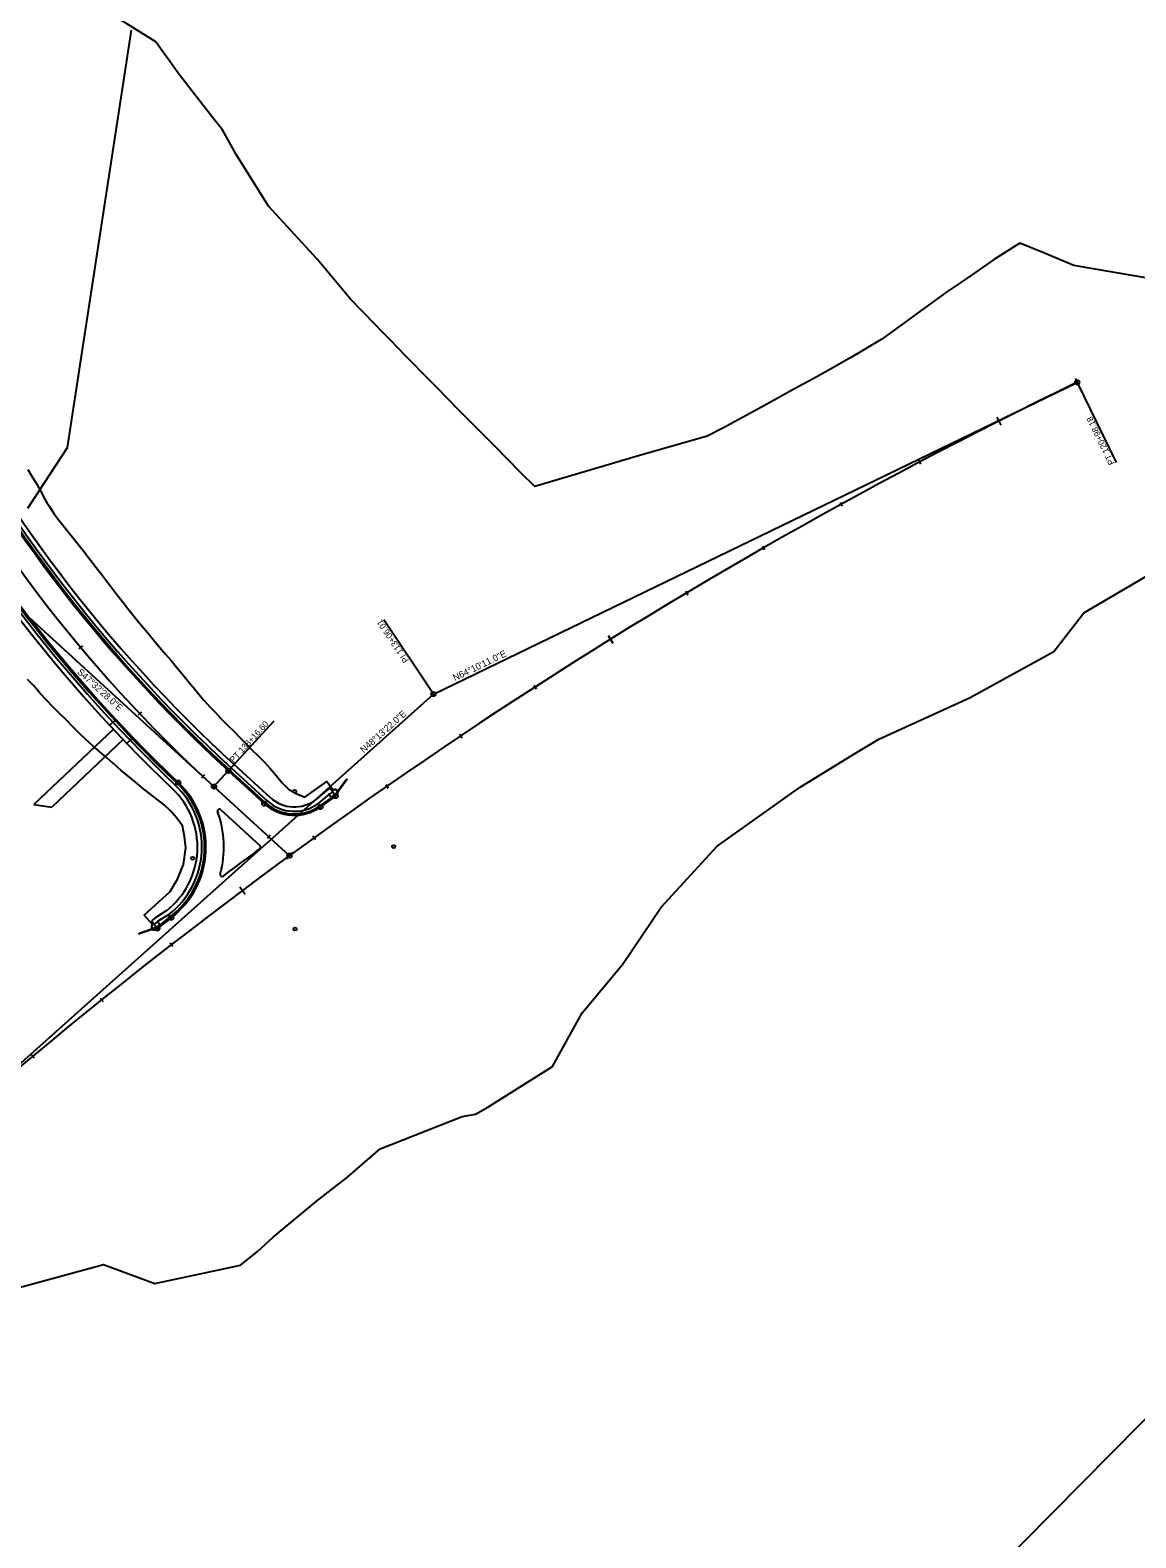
# Model space of a CAD drawing. Extents: x 1300404 to 1323571, y 234004 to 252077.
# Drawn here: x 1312432 to 1313673, y 237950 to 239641 of the extents above; entities that cross this region are included whole.
import ezdxf

# ---------------------------------------------------------------- set-up
doc = ezdxf.new("R2010")
doc.units = 0
for name, color, linetype in [('R_BRIDGE OLD', 7, 'Continuous'), ('R_Const Limits', 7, 'Continuous'), ('R_Curb', 7, 'Continuous'), ('R_Flooplain', 7, 'Continuous'), ('R_Horz Alg Annot', 7, 'Continuous'), ('R_Horz Alg Annot Leader', 7, 'Continuous'), ('R_Horz Alg Major Ticks', 7, 'Continuous'), ('R_Horz Alg Minor Ticks', 7, 'Continuous'), ('R_Horz Alg Tangents', 7, 'Continuous'), ('R_Horz Alg Tangents Text', 7, 'Continuous'), ('R_Information', 7, 'Continuous'), ('R_Lane Edge', 7, 'Continuous'), ('R_Proposed', 7, 'Continuous'), ('R_Sidewalk Edge', 7, 'Continuous')]:
    doc.layers.add(name, color=color, linetype=linetype)

msp = doc.modelspace()

# ---------------------------------------------------------------- linework, layer by layer
at = {"layer": 'R_BRIDGE OLD'}
for p, q in [((1312772.2, 238789.2), (1312772.5, 238788.8)), ((1312775, 238782.6), (1312775.9, 238783.9)), ((1312776.2, 238783.5), (1312775, 238782.6)), ((1312569.7, 238638.5), (1312570, 238638.1)), ((1312575.2, 238633.8), (1312573.7, 238633.3)), ((1312574, 238632.9), (1312575.2, 238633.8))]:
    msp.add_line(p, q, dxfattribs=at)
for centre, radius, start, end in [((1312774.2, 238786.3), 3.5, 305.0556, 125.0556), ((1312774.2, 238786.3), 3, 305.0556, 125.0556), ((1312571.8, 238635.7), 3.5, 127.9521, 307.9535), ((1312571.8, 238635.7), 3, 127.9521, 307.9535)]:
    msp.add_arc(centre, radius, start, end, dxfattribs=at)
at = {"layer": 'R_Const Limits'}
for points in [[(1313721.3, 239357.3), (1313603.3, 239377.4), (1313568.4, 239392.2), (1313542.7, 239402.7), (1313513.2, 239384), (1313489.8, 239367.4), (1313476.7, 239358.4), (1313460.8, 239348.1), (1313387.9, 239295), (1313375.3, 239287.5), (1313362.8, 239279.9), (1313351.3, 239273), (1313327.1, 239259.2), (1313310.9, 239250.5), (1313294.7, 239241.8), (1313282.6, 239235.1), (1313270.5, 239228.4), (1313252.1, 239218.2), (1313231.5, 239207), (1313209.5, 239195.2), (1313191.8, 239186.1), (1313112.2, 239163.2), (1312998.5, 239129.5), (1312983.4, 239144.7), (1312968.3, 239160), (1312953.2, 239175.2), (1312938.1, 239190.5), (1312925.8, 239202.9), (1312913.5, 239215.3), (1312901.3, 239227.7), (1312889, 239240.1), (1312880.3, 239249), (1312871.5, 239258), (1312862.8, 239266.9), (1312854, 239275.9), (1312845.3, 239284.8), (1312836.5, 239293.7), (1312827.8, 239302.7), (1312819, 239311.6), (1312805.5, 239325.6), (1312791.9, 239339.6), (1312754.5, 239384.7), (1312699.8, 239444), (1312663.1, 239502.8), (1312648.1, 239529.7), (1312637.5, 239543.2), (1312626.8, 239556.6), (1312616.2, 239570.1), (1312597.4, 239594.7), (1312589.3, 239605.9), (1312581.2, 239617.1), (1312573.2, 239628.3), (1312490, 239680.6)], [(1312429.6, 239148.6), (1312434.6, 239140.4), (1312439.8, 239132.4), (1312444.4, 239124), (1312448.8, 239115.4), (1312451.4, 239111.1), (1312453.9, 239107.2), (1312459.1, 239099.2), (1312464.8, 239091.5), (1312470.8, 239084), (1312476.9, 239076.6), (1312483, 239069.2), (1312489, 239061.7), (1312494.8, 239054.1), (1312495, 239053.9), (1312500.6, 239046.5), (1312506.4, 239038.9), (1312512.3, 239031.3), (1312518.1, 239023.7), (1312523.9, 239016.1), (1312529.7, 239008.5), (1312535.6, 239000.9), (1312541.5, 238993.3), (1312547.4, 238985.8), (1312553.4, 238978.3), (1312559.6, 238971), (1312565.7, 238963.6), (1312571.9, 238956.3), (1312578, 238948.9), (1312584.2, 238941.6), (1312590.5, 238934.3), (1312596.7, 238927), (1312602.9, 238919.6), (1312609, 238912.2), (1312614.5, 238905.4), (1312615.1, 238904.7), (1312621.2, 238897.2), (1312627.4, 238889.8), (1312633.8, 238882.6), (1312640.5, 238875.7), (1312647.2, 238868.8), (1312653.9, 238861.9), (1312660.7, 238855), (1312667.5, 238848.2), (1312674.2, 238841.3), (1312681.2, 238834.4), (1312688.3, 238827.4), (1312695.4, 238820.4), (1312702, 238812.8), (1312708.6, 238805.2), (1312715.1, 238797.4), (1312722.1, 238790.3), (1312730.9, 238785.1), (1312740.7, 238781), (1312765.1, 238798.7), (1312772.2, 238789.2)], [(1312411.7, 238228.8), (1312514.5, 238257), (1312572.3, 238235.7), (1312668.4, 238256.2), (1312687.4, 238271.7), (1312705.1, 238287.6), (1312753.1, 238327.5), (1312770, 238340.9), (1312788.5, 238355), (1312797.2, 238362.5), (1312825.2, 238386.7), (1312917.2, 238422.9), (1312932.2, 238425.5), (1312945.7, 238433.4), (1313018.6, 238478.9), (1313051.6, 238539.2), (1313096.8, 238593.6), (1313140.4, 238657.9), (1313203.3, 238726.1), (1313296.4, 238792.5), (1313358.3, 238830.6), (1313384.4, 238846.3), (1313487, 238893.1), (1313581.1, 238944.5), (1313614.6, 238987.9), (1313685.9, 239029.9)], [(1312569.7, 238638.5), (1312560.2, 238648.8), (1312589.3, 238675.5), (1312597.7, 238689), (1312604.3, 238705.6), (1312607, 238724.5), (1312605.7, 238737.2), (1312603.1, 238749.1), (1312597.1, 238757.7), (1312590.3, 238765.5), (1312582.7, 238772.5), (1312574.5, 238778.9), (1312566.2, 238785.2), (1312558, 238791.6), (1312550, 238798.2), (1312542.1, 238804.9), (1312534.1, 238811.6), (1312526.3, 238818.4), (1312525.5, 238819.1), (1312518.4, 238825.2), (1312510.5, 238832.1), (1312502.6, 238838.9), (1312494.7, 238845.7), (1312487.2, 238852.9), (1312479.9, 238860.3), (1312472.6, 238867.8), (1312465.1, 238875), (1312457.9, 238882.5), (1312450.7, 238890.1), (1312443.4, 238897.6), (1312436.7, 238905.6), (1312429.4, 238913)]]:
    msp.add_lwpolyline(points, dxfattribs=at)
at = {"layer": 'R_Curb'}
for p, q in [((1312655.5, 238811.4), (1312695.7, 238774.6)), ((1312655.8, 238811.8), (1312696.1, 238775)), ((1312774.6, 238783.2), (1312788.2, 238801.6)), ((1312775, 238784.6), (1312786.9, 238800.8)), ((1312788.2, 238801.6), (1312786.9, 238800.8)), ((1312774.6, 238783.2), (1312775, 238784.6)), ((1312770.5, 238780.3), (1312753.4, 238768.9)), ((1312756.9, 238770.6), (1312770.5, 238780.3)), ((1312578.5, 238637.8), (1312589.4, 238646.9)), ((1312588.4, 238645.5), (1312578.5, 238637.8)), ((1312574.5, 238634.7), (1312553.8, 238627.4)), ((1312553.8, 238627.4), (1312554.9, 238628.3)), ((1312572.9, 238634.7), (1312554.9, 238628.3)), ((1312574.5, 238634.7), (1312572.9, 238634.7))]:
    msp.add_line(p, q, dxfattribs=at)
for centre, radius, start, end in [((1313743.7, 240000.7), 1612, 206.7964, 227.5411), ((1313743.7, 240000.7), 1611.5, 206.7964, 227.5411), ((1313743.7, 240000.7), 1662.5, 206.7964, 226.4144), ((1313743.7, 240000.7), 1662, 206.7964, 226.4144), ((1312529.6, 238725.1), 99, 306.4353, 46.4144), ((1312529.6, 238725.1), 98.5, 307.3917, 46.4144), ((1312728.8, 238810.8), 49, 227.5411, 305.5569), ((1312728.8, 238810.8), 48.5, 227.5411, 300.4504)]:
    msp.add_arc(centre, radius, start, end, dxfattribs=at)
at = {"layer": 'R_Flooplain'}
for p, q in [((1312474.4, 239173.3), (1312546.1, 239641.5)), ((1312429.9, 239105.3), (1312474.4, 239173.3)), ((1313450, 237847.8), (1313753.2, 238154.3))]:
    msp.add_line(p, q, dxfattribs=at)
at = {"layer": 'R_Horz Alg Annot Leader'}
for points in [[(1313607.2, 239246.4), (1313650.8, 239156.4)], [(1312884.9, 238896.8), (1312829.2, 238979.9)], [(1312638.6, 238793), (1312706.1, 238866.7)]]:
    msp.add_lwpolyline(points, dxfattribs=at)
at = {"layer": 'R_Horz Alg Major Ticks'}
for points in [[(1313605, 239250.9), (1313609.4, 239241.9)], [(1313517, 239207.4), (1313521.5, 239198.5)], [(1313080.7, 238962.5), (1313086, 238954)], [(1312726.7, 238719.2), (1312719.9, 238711.8)], [(1312726.7, 238719.2), (1312719.9, 238711.8)], [(1312667.5, 238680.5), (1312673.5, 238672.4)]]:
    msp.add_lwpolyline(points, dxfattribs=at)
at = {"layer": 'R_Horz Alg Minor Ticks'}
for points in [[(1313429.2, 239159.2), (1313431.5, 239154.8)], [(1313341.1, 239111.8), (1313343.5, 239107.4)], [(1313253.9, 239062.8), (1313256.4, 239058.5)], [(1313167.5, 239012.3), (1313170.1, 239008)], [(1312490.9, 238950.9), (1312487, 238947.7)], [(1312997.5, 238906.9), (1313000.2, 238902.7)], [(1312557.3, 238876.4), (1312553.7, 238873)], [(1312913.9, 238851.9), (1312916.7, 238847.8)], [(1312628.1, 238806.1), (1312624.7, 238802.4)], [(1312831.3, 238795.5), (1312834.1, 238791.4)], [(1312701.8, 238738.5), (1312698.5, 238734.8)], [(1312749.6, 238737.7), (1312752.6, 238733.6)], [(1312589.5, 238617.8), (1312592.5, 238613.9)], [(1312511, 238555.8), (1312514.1, 238551.9)], [(1312433.6, 238492.4), (1312436.8, 238488.6)]]:
    msp.add_lwpolyline(points, dxfattribs=at)
at = {"layer": 'R_Horz Alg Tangents'}
for p, q in [((1312884.9, 238896.8), (1313607.2, 239246.4)), ((1312417.6, 238995.2), (1312638.6, 238793)), ((1312286.4, 238362.1), (1312884.9, 238896.8))]:
    msp.add_line(p, q, dxfattribs=at)
at = {"layer": 'R_Information'}
for p, q in [((1312528.5, 238868.4), (1312521.6, 238861.8)), ((1312525.7, 238857.4), (1312436.5, 238772.9)), ((1312547.7, 238848), (1312540.8, 238841.5)), ((1312536.7, 238845.8), (1312456.7, 238770)), ((1312436.5, 238772.9), (1312456.7, 238770))]:
    msp.add_line(p, q, dxfattribs=at)
at = {"layer": 'R_Lane Edge'}
for p, q in [((1312654.8, 238810.7), (1312695, 238773.9)), ((1312646, 238767.3), (1312690.4, 238726.6))]:
    msp.add_line(p, q, dxfattribs=at)
for centre, radius, start, end in [((1313743.7, 240000.7), 1613, 206.7964, 227.5411), ((1313743.7, 240000.7), 1661, 206.7964, 226.4144), ((1312529.6, 238725.1), 100, 307.6311, 46.4144), ((1316103.6, 234089.3), 5753.6, 125.34557, 125.55687), ((1312644.6, 238765.8), 2, 47.5411, 199.481), ((1312529.6, 238725.1), 120, 345.3657, 19.481), ((1312728.8, 238810.8), 50, 227.5411, 305.5569), ((1316103.6, 234089.3), 5755.6, 126.37407, 126.88804), ((1312689.1, 238725.1), 2, 306.3741, 47.5411), ((1312647.6, 238694.3), 2, 165.3657, 306.888), ((1316103.6, 234089.3), 5753.6, 127.63107, 127.82654)]:
    msp.add_arc(centre, radius, start, end, dxfattribs=at)
at = {"layer": 'R_Proposed'}
for p, q in [((1312654.8, 238810.7), (1312695, 238773.9)), ((1312638.6, 238793), (1312723.3, 238715.5))]:
    msp.add_line(p, q, dxfattribs=at)
for centre, radius in [((1313607.2, 239246.4), 2.5), ((1312884.9, 238896.8), 2.5), ((1312598.5, 238797.5), 2.5), ((1312654.8, 238810.7), 2.5), ((1312638.6, 238793), 2.5), ((1312729.1, 238787.6), 1.75), ((1312775.2, 238782.4), 2.5), ((1312695, 238773.9), 2.5), ((1312757.9, 238770.1), 2.5), ((1312614.8, 238712.6), 1.75), ((1312723.3, 238715.5), 2.5), ((1312840.3, 238725.7), 1.75), ((1312590.6, 238645.9), 2.5), ((1312575.1, 238633.9), 2.5), ((1312729.5, 238633.2), 1.75)]:
    msp.add_circle(centre, radius, dxfattribs=at)
for centre, radius, start, end in [((1313743.7, 240000.7), 1613, 206.7964, 227.5411), ((1313743.7, 240000.7), 1637, 206.7964, 227.5411), ((1313743.7, 240000.7), 1637, 206.7964, 227.5411), ((1313743.7, 240000.7), 1661, 206.7964, 226.4144), ((1316103.6, 234089.3), 5729.6, 115.83028, 131.77722), ((1312529.6, 238725.1), 100, 307.6311, 46.4144), ((1316103.6, 234089.3), 5753.6, 125.34557, 125.55687), ((1312728.8, 238810.8), 50, 227.5411, 305.5569), ((1316103.6, 234089.3), 5753.6, 127.63107, 127.82654)]:
    msp.add_arc(centre, radius, start, end, dxfattribs=at)
at = {"layer": 'R_Sidewalk Edge'}
for p, q in [((1312661.2, 238817.7), (1312701.5, 238780.9)), ((1312657.9, 238814), (1312698.1, 238777.2)), ((1312753.1, 238778.4), (1312764.8, 238788.4)), ((1312756.2, 238774.4), (1312767.7, 238784.3)), ((1312764.8, 238788.4), (1312768.9, 238791.3)), ((1312767.7, 238784.3), (1312771.1, 238779.5)), ((1312768.9, 238791.3), (1312775.2, 238782.4)), ((1312572.3, 238645.6), (1312568.4, 238642.6)), ((1312585.1, 238653.7), (1312572.3, 238645.6)), ((1312588, 238649.6), (1312575.4, 238641.7)), ((1312568.4, 238642.6), (1312575.1, 238633.9)), ((1312575.4, 238641.7), (1312579.1, 238637))]:
    msp.add_line(p, q, dxfattribs=at)
for centre, radius, start, end in [((1313743.7, 240000.7), 1608.5, 206.7964, 227.5411), ((1313743.7, 240000.7), 1603.5, 206.7964, 227.5411), ((1313743.7, 240000.7), 1670.5, 206.7964, 226.4144), ((1313743.7, 240000.7), 1665.5, 206.7964, 226.4144), ((1312529.6, 238725.1), 90.5, 307.6311, 46.4144), ((1312529.6, 238725.1), 95.5, 307.6311, 46.4144), ((1312728.8, 238810.8), 40.5, 227.5411, 307.1955), ((1316081.1, 234073.3), 5759.6, 125.0706, 125.12034), ((1316081.1, 234073.3), 5755.6, 125.07046, 125.12023), ((1312728.8, 238810.8), 45.5, 227.5411, 306.9778), ((1316112.6, 234096.2), 5759.6, 127.88874, 127.93848), ((1316112.6, 234096.2), 5755.6, 127.88885, 127.93862)]:
    msp.add_arc(centre, radius, start, end, dxfattribs=at)

# ---------------------------------------------------------------- texts
at = {"layer": 'R_Horz Alg Annot'}
for s, rotation, p in [('PT 120+98.18', 115.8303, (1313649.4, 239155.8)), ('PI 113+06.01', 123.8038, (1312857.6, 238934.8)), ('PT 138+16.60', 47.5411, (1312660.6, 238819.2))]:
    msp.add_text(s, height=7, rotation=rotation, dxfattribs=at).set_placement(p)
at = {"layer": 'R_Horz Alg Tangents Text'}
for s, rotation, p in [('N64%%d10\'11.0"E', 25.8303, (1312908.9, 238911.2)), ('S47%%d32\'28.0"E', 317.5411, (1312484.5, 238920.7)), ('N48%%d13\'22.0"E', 41.7772, (1312806.6, 238830.2))]:
    msp.add_text(s, height=7.5, rotation=rotation, dxfattribs=at).set_placement(p)

doc.saveas('drawing.dxf')
